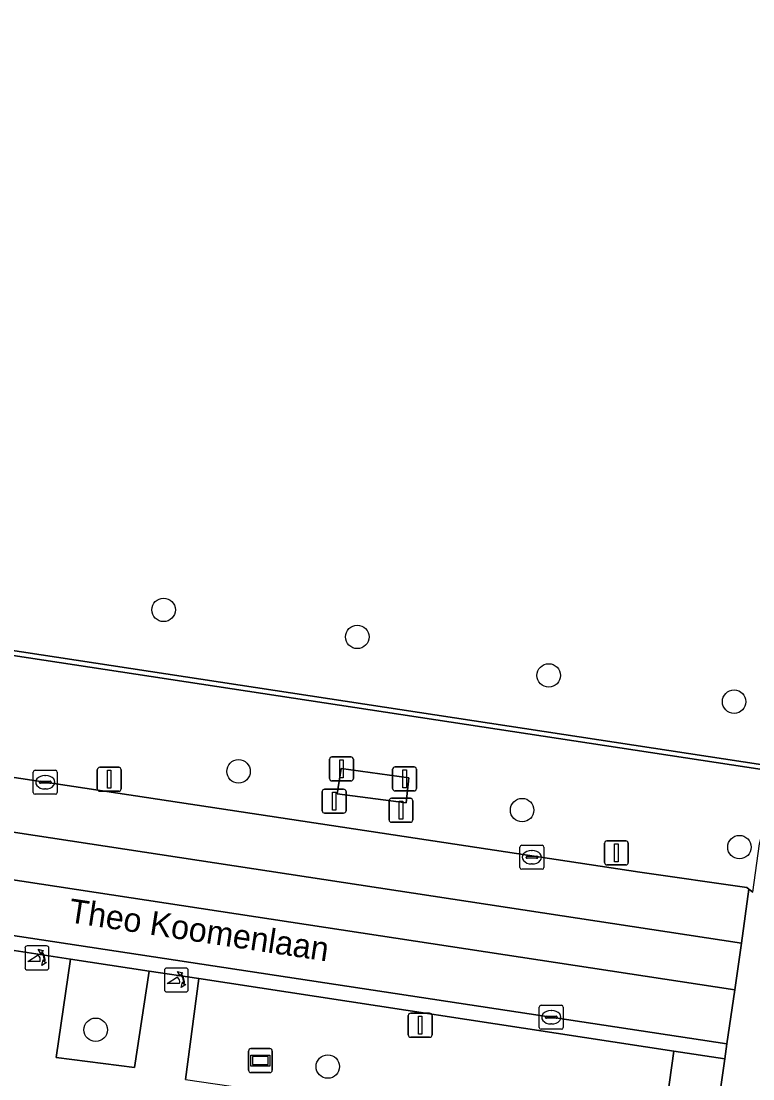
# Model space of a CAD drawing. Extents: x 161090 to 161692, y 379509 to 380907.
# Drawn here: x 161555.75 to 161586.23, y 380431.93 to 380476 of the extents above; entities that cross this region are included whole.
import ezdxf

# ---------------------------------------------------------------- set-up
doc = ezdxf.new("R2010")
doc.units = 0
for name, color, linetype in [('IMGEO_Afsluitpaal', 7, 'Continuous'), ('IMGEO_Boom', 7, 'Continuous'), ('IMGEO_Groenvoorziening', 7, 'Continuous'), ('IMGEO_Hek', 7, 'Continuous'), ('IMGEO_Kolk', 7, 'Continuous'), ('IMGEO_Lichtmast', 7, 'Continuous'), ('IMGEO_Loofbos', 7, 'Continuous'), ('IMGEO_Openbare_ruimte_label', 7, 'Continuous'), ('IMGEO_Poller', 7, 'Continuous'), ('IMGEO_Rijbaan_lokaal_gesloten', 7, 'Continuous'), ('IMGEO_Rijbaan_lokaal_open', 7, 'Continuous'), ('IMGEO_Rioolput', 7, 'Continuous'), ('IMGEO_Terreindeel_gesloten', 7, 'Continuous'), ('IMGEO_Verklikker', 7, 'Continuous'), ('IMGEO_Voetpad_open', 7, 'Continuous')]:
    doc.layers.add(name, color=color, linetype=linetype)

msp = doc.modelspace()

# ---------------------------------------------------------------- linework, layer by layer
at = {"layer": 'IMGEO_Afsluitpaal'}
for p, q in [((161568.6, 380444.443), (161568.6, 380445.243)), ((161568.6, 380445.243), (161568.6, 380444.443)), ((161568.7, 380445.343), (161569.49, 380445.343)), ((161569.49, 380445.343), (161568.7, 380445.343)), ((161569.59, 380445.243), (161569.59, 380444.443)), ((161569.59, 380444.443), (161569.59, 380445.243)), ((161571.227, 380444.025), (161571.227, 380444.825)), ((161571.227, 380444.825), (161571.227, 380444.025)), ((161571.327, 380444.925), (161572.117, 380444.925)), ((161572.117, 380444.925), (161571.327, 380444.925)), ((161572.217, 380444.825), (161572.217, 380444.025)), ((161572.217, 380444.025), (161572.217, 380444.825)), ((161569.49, 380444.343), (161568.7, 380444.343)), ((161568.7, 380444.343), (161569.49, 380444.343)), ((161568.294, 380443.099), (161568.294, 380443.899)), ((161568.294, 380443.899), (161568.294, 380443.099)), ((161568.394, 380443.999), (161569.184, 380443.999)), ((161569.184, 380443.999), (161568.394, 380443.999)), ((161569.284, 380443.899), (161569.284, 380443.099)), ((161569.284, 380443.099), (161569.284, 380443.899)), ((161572.117, 380443.925), (161571.327, 380443.925)), ((161571.327, 380443.925), (161572.117, 380443.925)), ((161571.075, 380442.718), (161571.075, 380443.518)), ((161571.075, 380443.518), (161571.075, 380442.718)), ((161571.175, 380443.618), (161571.965, 380443.618)), ((161571.965, 380443.618), (161571.175, 380443.618)), ((161572.065, 380443.518), (161572.065, 380442.718)), ((161572.065, 380442.718), (161572.065, 380443.518)), ((161569.184, 380442.999), (161568.394, 380442.999)), ((161568.394, 380442.999), (161569.184, 380442.999)), ((161571.965, 380442.618), (161571.175, 380442.618)), ((161571.175, 380442.618), (161571.965, 380442.618))]:
    msp.add_line(p, q, dxfattribs=at)
for points in [[(161569.02, 380445.218), (161569.17, 380445.218), (161569.17, 380444.468), (161569.02, 380444.468), (161569.02, 380445.218)], [(161571.647, 380444.8), (161571.797, 380444.8), (161571.797, 380444.05), (161571.647, 380444.05), (161571.647, 380444.8)], [(161568.714, 380443.874), (161568.864, 380443.874), (161568.864, 380443.124), (161568.714, 380443.124), (161568.714, 380443.874)], [(161571.495, 380443.493), (161571.645, 380443.493), (161571.645, 380442.743), (161571.495, 380442.743), (161571.495, 380443.493)]]:
    msp.add_lwpolyline(points, dxfattribs=at)
for centre, start, end in [((161568.7, 380445.243), 90, 180), ((161568.7, 380445.243), 90, 180), ((161569.49, 380445.243), 0, 90), ((161569.49, 380445.243), 360, 90), ((161571.327, 380444.825), 90, 180), ((161571.327, 380444.825), 90, 180), ((161572.117, 380444.825), 0, 90), ((161572.117, 380444.825), 360, 90), ((161568.7, 380444.443), 180, 270), ((161568.7, 380444.443), 180, 270), ((161569.49, 380444.443), 270, 0), ((161569.49, 380444.443), 270, 0), ((161568.394, 380443.899), 90, 180), ((161568.394, 380443.899), 90, 180), ((161569.184, 380443.899), 0, 90), ((161569.184, 380443.899), 360, 90), ((161571.327, 380444.025), 180, 270), ((161571.327, 380444.025), 180, 270), ((161572.117, 380444.025), 270, 0), ((161572.117, 380444.025), 270, 0), ((161571.175, 380443.518), 90, 180), ((161571.175, 380443.518), 90, 180), ((161571.965, 380443.518), 0, 90), ((161571.965, 380443.518), 360, 90), ((161568.394, 380443.099), 180, 270), ((161568.394, 380443.099), 180, 270), ((161569.184, 380443.099), 270, 0), ((161569.184, 380443.099), 270, 0), ((161571.175, 380442.718), 180, 270), ((161571.175, 380442.718), 180, 270), ((161571.965, 380442.718), 270, 0), ((161571.965, 380442.718), 270, 0)]:
    msp.add_arc(centre, 0.1, start, end, dxfattribs=at)
at = {"layer": 'IMGEO_Boom'}
for centre in [(161561.685, 380451.469), (161569.753, 380450.342), (161577.728, 380448.738), (161585.45, 380447.643), (161564.807, 380444.74), (161576.619, 380443.126), (161585.672, 380441.584), (161558.855, 380433.974), (161568.524, 380432.44)]:
    msp.add_circle(centre, 0.489, dxfattribs=at)
at = {"layer": 'IMGEO_Groenvoorziening'}
for points in [[(161434.436, 380467.982), (161587.251, 380444.727), (161587.284, 380444.922), (161504.1, 380457.592), (161500, 380458.218), (161490.036, 380459.739), (161486.843, 380460.227), (161480.056, 380461.264), (161476.893, 380461.747), (161462.434, 380463.956), (161459.238, 380464.445), (161450.466, 380465.785), (161447.798, 380466.193), (161437.88, 380467.708), (161434.68, 380468.197), (161434.559, 380468.215)], [(161557.811, 380436.921), (161557.203, 380432.816), (161560.473, 380432.408), (161561.082, 380436.422)], [(161582.946, 380433.087), (161563.155, 380436.106), (161562.595, 380431.908), (161582.37, 380429.013)]]:
    msp.add_lwpolyline(points, close=True, dxfattribs=at)
at = {"layer": 'IMGEO_Hek'}
msp.add_lwpolyline([(161587.251, 380444.727), (161434.436, 380467.982)], dxfattribs=at)
at = {"layer": 'IMGEO_Kolk'}
for p, q in [((161556.331, 380444.787), (161557.183, 380444.787)), ((161556.256, 380443.861), (161556.256, 380444.713)), ((161556.558, 380444.33), (161556.956, 380444.33)), ((161556.744, 380444.567), (161556.769, 380444.567)), ((161557.257, 380444.713), (161557.257, 380443.861)), ((161556.515, 380444.281), (161556.515, 380444.293)), ((161556.953, 380444.244), (161556.555, 380444.244)), ((161556.767, 380444.007), (161556.742, 380444.007)), ((161556.999, 380444.293), (161556.999, 380444.281)), ((161557.183, 380443.787), (161556.331, 380443.787)), ((161576.602, 380441.662), (161577.454, 380441.662)), ((161576.527, 380440.736), (161576.527, 380441.588)), ((161577.015, 380441.442), (161577.04, 380441.442)), ((161577.528, 380441.588), (161577.528, 380440.736)), ((161576.786, 380441.156), (161576.786, 380441.168)), ((161577.224, 380441.119), (161576.826, 380441.119)), ((161576.829, 380441.205), (161577.227, 380441.205)), ((161577.038, 380440.882), (161577.013, 380440.882)), ((161577.27, 380441.168), (161577.27, 380441.156)), ((161577.454, 380440.662), (161576.602, 380440.662))]:
    msp.add_line(p, q, dxfattribs=at)
for points in [[(161556.331, 380444.787), (161557.183, 380444.787)], [(161556.256, 380443.861), (161556.256, 380444.713)], [(161557.257, 380444.713), (161557.257, 380443.861)], [(161557.183, 380443.787), (161556.331, 380443.787)], [(161576.602, 380441.662), (161577.454, 380441.662)], [(161576.527, 380440.736), (161576.527, 380441.588)], [(161577.528, 380441.588), (161577.528, 380440.736)], [(161577.454, 380440.662), (161576.602, 380440.662)]]:
    msp.add_lwpolyline(points, dxfattribs=at)
for centre, radius, start, end in [((161556.333, 380444.711), 0.0765, 91.552, 178.448), ((161556.333, 380444.711), 0.0765, 91.552, 178.448), ((161557.181, 380444.711), 0.0765, 1.552, 88.448), ((161557.181, 380444.711), 0.0765, 1.552, 88.448), ((161556.555, 380444.29), 0.0403, 85.8775, 175.7526), ((161556.96, 380444.292), 0.0386, 1.7309, 96.639), ((161556.333, 380443.863), 0.0765, 181.552, 268.448), ((161556.333, 380443.863), 0.0765, 181.552, 268.448), ((161556.552, 380444.28), 0.0366, 178.938, 274.7102), ((161556.956, 380444.287), 0.043, 264.8664, 352.4533), ((161557.181, 380443.863), 0.0765, 271.552, 358.448), ((161557.181, 380443.863), 0.0765, 271.552, 358.448), ((161576.604, 380441.586), 0.0765, 91.552, 178.448), ((161576.604, 380441.586), 0.0765, 91.552, 178.448), ((161577.452, 380441.586), 0.0765, 1.552, 88.448), ((161577.452, 380441.586), 0.0765, 1.552, 88.448), ((161576.826, 380441.165), 0.0403, 85.8775, 175.7526), ((161576.823, 380441.155), 0.0366, 178.938, 274.7102), ((161577.227, 380441.162), 0.043, 264.8664, 352.4533), ((161577.231, 380441.167), 0.0386, 1.7309, 96.639), ((161576.604, 380440.738), 0.0765, 181.552, 268.448), ((161576.604, 380440.738), 0.0765, 181.552, 268.448), ((161577.452, 380440.738), 0.0765, 271.552, 358.448), ((161577.452, 380440.738), 0.0765, 271.552, 358.448)]:
    msp.add_arc(centre, radius, start, end, dxfattribs=at)
for centre, major_axis, ratio, start_param, end_param in [((161556.743, 380444.287), (-0.387, 0.002), 0.722429, 4.712389, 7.853982), ((161556.768, 380444.287), (-0.39, 0.002), 0.717154, 1.570796, 4.712389), ((161577.014, 380441.162), (-0.387, 0.002), 0.722429, 4.712389, 7.853982), ((161577.039, 380441.162), (-0.39, 0.002), 0.717154, 1.570796, 4.712389)]:
    msp.add_ellipse(centre, major_axis=major_axis, ratio=ratio, start_param=start_param, end_param=end_param, dxfattribs=at)
at = {"layer": 'IMGEO_Lichtmast'}
for p, q in [((161558.924, 380444.009), (161558.924, 380444.809)), ((161558.924, 380444.809), (161558.924, 380444.009)), ((161559.024, 380444.909), (161559.814, 380444.909)), ((161559.814, 380444.909), (161559.024, 380444.909)), ((161559.914, 380444.809), (161559.914, 380444.009)), ((161559.914, 380444.009), (161559.914, 380444.809)), ((161559.814, 380443.909), (161559.024, 380443.909)), ((161559.024, 380443.909), (161559.814, 380443.909)), ((161580.051, 380440.942), (161580.051, 380441.742)), ((161580.051, 380441.742), (161580.051, 380440.942)), ((161580.151, 380441.842), (161580.941, 380441.842)), ((161580.941, 380441.842), (161580.151, 380441.842)), ((161581.041, 380441.742), (161581.041, 380440.942)), ((161581.041, 380440.942), (161581.041, 380441.742)), ((161580.941, 380440.842), (161580.151, 380440.842)), ((161580.151, 380440.842), (161580.941, 380440.842)), ((161571.978, 380434.662), (161572.768, 380434.662)), ((161572.768, 380434.662), (161571.978, 380434.662)), ((161571.878, 380433.762), (161571.878, 380434.562)), ((161571.878, 380434.562), (161571.878, 380433.762)), ((161572.868, 380434.562), (161572.868, 380433.762)), ((161572.868, 380433.762), (161572.868, 380434.562)), ((161572.768, 380433.662), (161571.978, 380433.662)), ((161571.978, 380433.662), (161572.768, 380433.662))]:
    msp.add_line(p, q, dxfattribs=at)
for points in [[(161559.344, 380444.784), (161559.494, 380444.784), (161559.494, 380444.034), (161559.344, 380444.034), (161559.344, 380444.784)], [(161580.471, 380441.717), (161580.621, 380441.717), (161580.621, 380440.967), (161580.471, 380440.967), (161580.471, 380441.717)], [(161572.298, 380434.537), (161572.448, 380434.537), (161572.448, 380433.787), (161572.298, 380433.787), (161572.298, 380434.537)]]:
    msp.add_lwpolyline(points, dxfattribs=at)
for centre, start, end in [((161559.024, 380444.809), 90, 180), ((161559.024, 380444.809), 90, 180), ((161559.814, 380444.809), 0, 90), ((161559.814, 380444.809), 360, 90), ((161559.024, 380444.009), 180, 270), ((161559.024, 380444.009), 180, 270), ((161559.814, 380444.009), 270, 0), ((161559.814, 380444.009), 270, 0), ((161580.151, 380441.742), 90, 180), ((161580.151, 380441.742), 90, 180), ((161580.941, 380441.742), 0, 90), ((161580.941, 380441.742), 360, 90), ((161580.151, 380440.942), 180, 270), ((161580.151, 380440.942), 180, 270), ((161580.941, 380440.942), 270, 0), ((161580.941, 380440.942), 270, 0), ((161571.978, 380434.562), 90, 180), ((161571.978, 380434.562), 90, 180), ((161572.768, 380434.562), 0, 90), ((161572.768, 380434.562), 360, 90), ((161571.978, 380433.762), 180, 270), ((161571.978, 380433.762), 180, 270), ((161572.768, 380433.762), 270, 0), ((161572.768, 380433.762), 270, 0)]:
    msp.add_arc(centre, 0.1, start, end, dxfattribs=at)
at = {"layer": 'IMGEO_Loofbos'}
for points in [[(161450.466, 380465.785), (161459.238, 380464.445), (161462.434, 380463.956), (161476.893, 380461.747), (161480.056, 380461.264), (161486.843, 380460.227), (161490.036, 380459.739), (161500, 380458.218), (161504.1, 380457.592), (161587.284, 380444.922), (161588.227, 380450.468), (161588.877, 380454.862), (161592.486, 380454.328), (161596.599, 380453.72), (161596.632, 380453.952), (161599.292, 380453.559), (161599.284, 380453.506), (161600.762, 380453.225), (161601.946, 380453.038), (161602.323, 380452.975), (161603.356, 380459.92), (161606.301, 380479.461), (161609.342, 380499.396)], [(161435.157, 380462.917), (161501.097, 380452.867), (161512.062, 380451.442), (161512, 380451.031), (161556.757, 380444.287), (161581.527, 380440.544), (161585.979, 380439.898), (161586.07, 380439.832), (161586.237, 380439.711), (161586.511, 380441.722), (161587.251, 380444.727), (161434.436, 380467.982)]]:
    msp.add_lwpolyline(points, dxfattribs=at)
msp.add_lwpolyline([(161569.08, 380444.865), (161571.895, 380444.469), (161571.783, 380443.435), (161568.916, 380443.804)], close=True, dxfattribs=at)
at = {"layer": 'IMGEO_Poller'}
for p, q in [((161555.912, 380437.372), (161555.912, 380436.565)), ((161555.912, 380437.372), (161555.912, 380436.565)), ((161556.814, 380437.467), (161556.006, 380437.467)), ((161556.814, 380437.467), (161556.006, 380437.467)), ((161556.908, 380436.565), (161556.908, 380437.372)), ((161556.908, 380436.565), (161556.908, 380437.372)), ((161556.006, 380436.47), (161556.814, 380436.47)), ((161556.006, 380436.47), (161556.814, 380436.47)), ((161561.717, 380436.451), (161561.717, 380435.644)), ((161561.717, 380436.451), (161561.717, 380435.644)), ((161562.619, 380436.546), (161561.811, 380436.546)), ((161562.619, 380436.546), (161561.811, 380436.546)), ((161562.713, 380435.644), (161562.713, 380436.451)), ((161562.713, 380435.644), (161562.713, 380436.451)), ((161561.811, 380435.549), (161562.619, 380435.549)), ((161561.811, 380435.549), (161562.619, 380435.549))]:
    msp.add_line(p, q, dxfattribs=at)
for points in [[(161556.591, 380437.196), (161556.579, 380437.123), (161556.454, 380437.328)], [(161556.454, 380437.328), (161556.685, 380437.262), (161556.614, 380437.23)], [(161556.547, 380436.823), (161556.034, 380436.823), (161556.464, 380437.098)], [(161556.607, 380436.651), (161556.673, 380436.882), (161556.703, 380436.814)], [(161556.739, 380436.787), (161556.811, 380436.776), (161556.607, 380436.651)], [(161562.396, 380436.275), (161562.384, 380436.202), (161562.259, 380436.407)], [(161562.259, 380436.407), (161562.49, 380436.341), (161562.419, 380436.309)], [(161562.352, 380435.902), (161561.839, 380435.902), (161562.269, 380436.177)], [(161562.412, 380435.73), (161562.478, 380435.961), (161562.508, 380435.893)], [(161562.544, 380435.866), (161562.616, 380435.855), (161562.412, 380435.73)]]:
    msp.add_lwpolyline(points, dxfattribs=at)
for centre, radius, start, end in [((161556.006, 380437.372), 0.0946, 90, 180), ((161556.006, 380437.372), 0.0946, 90, 180), ((161556.814, 380437.372), 0.0946, 0, 90), ((161556.814, 380437.372), 0.0946, 0, 90), ((161556.219, 380436.873), 0.332, 351.3247, 42.4854), ((161556.233, 380436.883), 0.476, 351.7527, 41.1691), ((161556.233, 380436.883), 0.516, 349.3569, 42.2912), ((161556.006, 380436.565), 0.0946, 180, 270), ((161556.006, 380436.565), 0.0946, 180, 270), ((161556.814, 380436.565), 0.0946, 270, 0), ((161556.814, 380436.565), 0.0946, 270, 0), ((161561.811, 380436.451), 0.0946, 90, 180), ((161561.811, 380436.451), 0.0946, 90, 180), ((161562.619, 380436.451), 0.0946, 0, 90), ((161562.619, 380436.451), 0.0946, 0, 90), ((161562.024, 380435.952), 0.332, 351.3247, 42.4854), ((161562.038, 380435.962), 0.476, 351.7527, 41.1691), ((161562.038, 380435.962), 0.516, 349.3569, 42.2912), ((161561.811, 380435.644), 0.0946, 180, 270), ((161561.811, 380435.644), 0.0946, 180, 270), ((161562.619, 380435.644), 0.0946, 270, 0), ((161562.619, 380435.644), 0.0946, 270, 0)]:
    msp.add_arc(centre, radius, start, end, dxfattribs=at)
at = {"layer": 'IMGEO_Rijbaan_lokaal_gesloten'}
for points in [[(161504.951, 380449.901), (161585.752, 380437.576), (161586.07, 380439.832), (161585.979, 380439.898), (161581.527, 380440.544), (161556.757, 380444.287), (161512, 380451.031), (161511.989, 380450.855), (161501.011, 380452.274), (161450.119, 380460.069), (161403.689, 380467.027), (161366.753, 380472.715), (161350.026, 380475.243), (161349.305, 380475.322)], [(161508.463, 380445.032), (161509.279, 380444.908), (161585.149, 380433.385), (161585.474, 380435.644), (161504.655, 380447.955), (161504.951, 380449.901)]]:
    msp.add_lwpolyline(points, dxfattribs=at)
at = {"layer": 'IMGEO_Rijbaan_lokaal_open'}
for points in [[(161585.474, 380435.644), (161585.752, 380437.576), (161504.951, 380449.901), (161504.655, 380447.955)], [(161509.279, 380444.908), (161509.185, 380444.339), (161534.794, 380440.432), (161536.957, 380440.102), (161540.219, 380439.605), (161547.555, 380438.486), (161550.751, 380437.998), (161557.811, 380436.921), (161561.082, 380436.422), (161563.155, 380436.106), (161582.946, 380433.087), (161585.06, 380432.764), (161585.149, 380433.385)]]:
    msp.add_lwpolyline(points, close=True, dxfattribs=at)
at = {"layer": 'IMGEO_Rioolput'}
for p, q in [((161577.335, 380434.069), (161577.335, 380434.921)), ((161577.41, 380434.995), (161578.262, 380434.995)), ((161577.823, 380434.775), (161577.848, 380434.775)), ((161578.336, 380434.921), (161578.336, 380434.069)), ((161577.594, 380434.489), (161577.594, 380434.501)), ((161578.032, 380434.452), (161577.634, 380434.452)), ((161577.637, 380434.538), (161578.035, 380434.538)), ((161577.846, 380434.215), (161577.821, 380434.215)), ((161578.078, 380434.501), (161578.078, 380434.489)), ((161578.262, 380433.995), (161577.41, 380433.995))]:
    msp.add_line(p, q, dxfattribs=at)
for points in [[(161577.335, 380434.069), (161577.335, 380434.921)], [(161577.41, 380434.995), (161578.262, 380434.995)], [(161578.336, 380434.921), (161578.336, 380434.069)], [(161578.262, 380433.995), (161577.41, 380433.995)]]:
    msp.add_lwpolyline(points, dxfattribs=at)
for centre, radius, start, end in [((161577.412, 380434.919), 0.0765, 91.552, 178.448), ((161577.412, 380434.919), 0.0765, 91.552, 178.448), ((161578.26, 380434.919), 0.0765, 1.552, 88.448), ((161578.26, 380434.919), 0.0765, 1.552, 88.448), ((161577.634, 380434.498), 0.0403, 85.8775, 175.7526), ((161577.631, 380434.488), 0.0366, 178.938, 274.7102), ((161578.035, 380434.495), 0.043, 264.8664, 352.4533), ((161578.039, 380434.5), 0.0386, 1.7309, 96.639), ((161577.412, 380434.071), 0.0765, 181.552, 268.448), ((161577.412, 380434.071), 0.0765, 181.552, 268.448), ((161578.26, 380434.071), 0.0765, 271.552, 358.448), ((161578.26, 380434.071), 0.0765, 271.552, 358.448)]:
    msp.add_arc(centre, radius, start, end, dxfattribs=at)
for centre, major_axis, ratio, start_param, end_param in [((161577.822, 380434.495), (-0.387, 0.002), 0.722429, 4.712389, 7.853982), ((161577.847, 380434.495), (-0.39, 0.002), 0.717154, 1.570796, 4.712389)]:
    msp.add_ellipse(centre, major_axis=major_axis, ratio=ratio, start_param=start_param, end_param=end_param, dxfattribs=at)
at = {"layer": 'IMGEO_Terreindeel_gesloten'}
msp.add_lwpolyline([(161568.916, 380443.804), (161571.783, 380443.435), (161571.895, 380444.469), (161569.08, 380444.865)], close=True, dxfattribs=at)
at = {"layer": 'IMGEO_Verklikker'}
for p, q in [((161565.222, 380432.289), (161565.222, 380433.089)), ((161565.222, 380433.089), (161565.222, 380432.289)), ((161565.322, 380433.189), (161566.112, 380433.189)), ((161566.112, 380433.189), (161565.322, 380433.189)), ((161566.212, 380433.089), (161566.212, 380432.289)), ((161566.212, 380432.289), (161566.212, 380433.089)), ((161566.112, 380432.189), (161565.322, 380432.189)), ((161565.322, 380432.189), (161566.112, 380432.189))]:
    msp.add_line(p, q, dxfattribs=at)
for points in [[(161565.323, 380432.921), (161566.111, 380432.921), (161566.111, 380432.457), (161565.323, 380432.457), (161565.323, 380432.921)], [(161565.388, 380432.856), (161565.388, 380432.522), (161566.046, 380432.522), (161566.046, 380432.856), (161565.388, 380432.856)]]:
    msp.add_lwpolyline(points, dxfattribs=at)
for centre, start, end in [((161565.322, 380433.089), 90, 180), ((161565.322, 380433.089), 90, 180), ((161566.112, 380433.089), 0, 90), ((161566.112, 380433.089), 360, 90), ((161565.322, 380432.289), 180, 270), ((161565.322, 380432.289), 180, 270), ((161566.112, 380432.289), 270, 0), ((161566.112, 380432.289), 270, 0)]:
    msp.add_arc(centre, 0.1, start, end, dxfattribs=at)
at = {"layer": 'IMGEO_Voetpad_open'}
for points in [[(161562.595, 380431.908), (161563.155, 380436.106), (161561.082, 380436.422), (161560.473, 380432.408), (161557.203, 380432.816), (161557.811, 380436.921), (161550.751, 380437.998), (161550.193, 380433.927), (161546.918, 380434.371), (161547.555, 380438.486), (161540.219, 380439.605), (161539.581, 380435.538), (161536.341, 380436.033), (161536.957, 380440.102), (161534.794, 380440.432)], [(161586.237, 380439.711), (161586.07, 380439.832), (161585.752, 380437.576), (161585.474, 380435.644), (161585.149, 380433.385), (161585.06, 380432.764), (161584.794, 380430.918)]]:
    msp.add_lwpolyline(points, dxfattribs=at)
msp.add_lwpolyline([(161584.794, 380430.918), (161585.06, 380432.764), (161582.946, 380433.087), (161582.37, 380429.013), (161584.476, 380428.705)], close=True, dxfattribs=at)

# ---------------------------------------------------------------- texts
at = {"layer": 'IMGEO_Openbare_ruimte_label'}
msp.add_text('Theo Koomenlaan', height=1, rotation=351.3758, dxfattribs=at).set_placement((161557.682, 380438.459))

doc.saveas('drawing.dxf')
